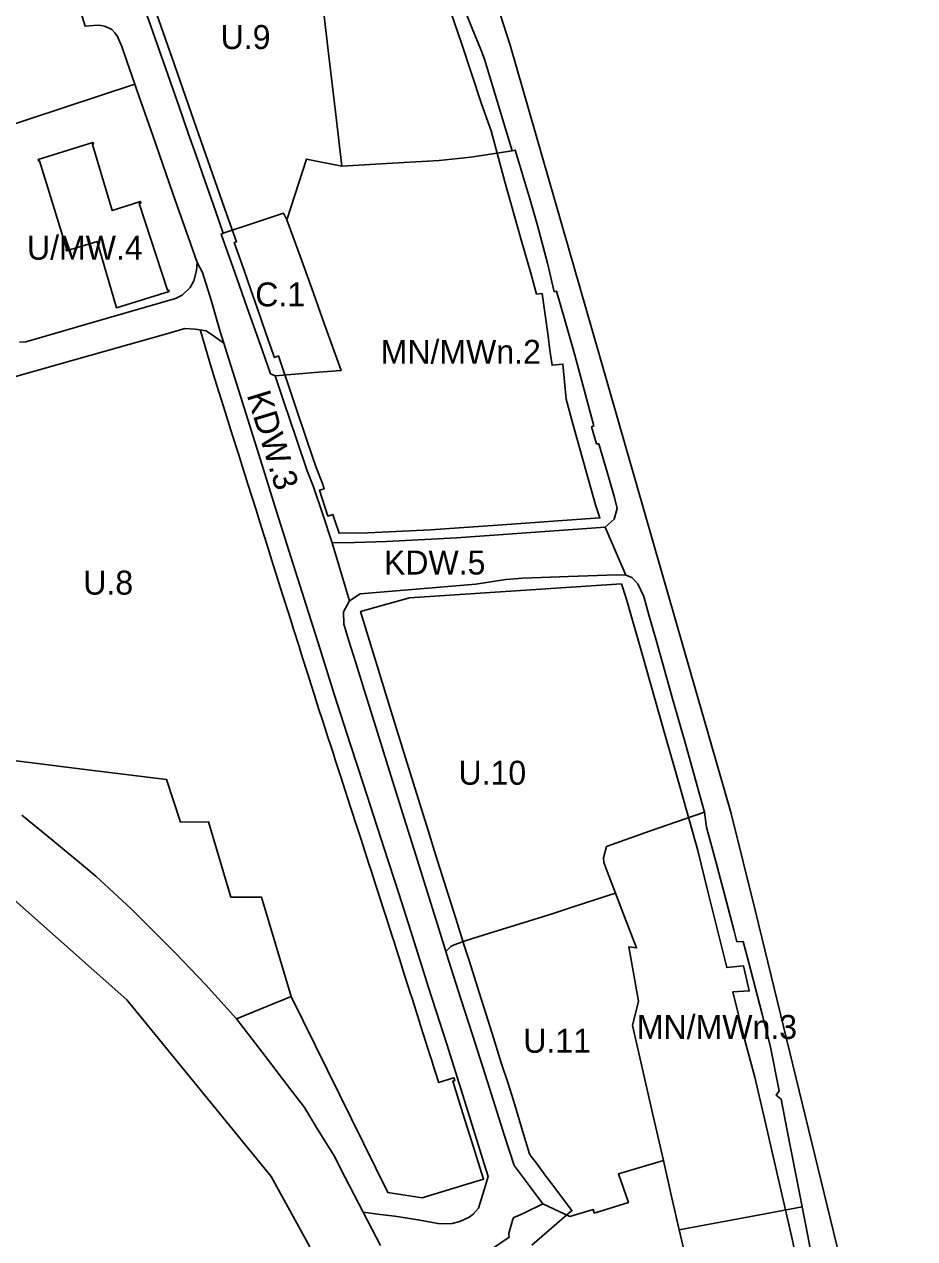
# Model space of a CAD drawing. Extents: x 7429178 to 7430831, y 5550228 to 5551611.
# Drawn here: x 7430325.9 to 7430511.7, y 5550756.2 to 5551009.6 of the extents above; entities that cross this region are included whole.
import ezdxf

# ---------------------------------------------------------------- set-up
doc = ezdxf.new("R2010")
doc.units = 0
for name, color, linetype in [('linie rozgraniczające', 7, 'Continuous'), ('nieprzekraczalne linie zabudowy', 7, 'Continuous'), ('obowiazujace linie zabudowy', 7, 'Continuous'), ('przeznaczenia terenów', 7, 'Continuous')]:
    doc.layers.add(name, color=color, linetype=linetype)

msp = doc.modelspace()

# ---------------------------------------------------------------- linework, layer by layer
at = {"layer": 'linie rozgraniczające'}
for points in [[(7430453.92, 5551228.43), (7430452.8, 5551207.06), (7430447.48, 5551184.97), (7430436.75, 5551167.9), (7430417.03, 5551148.36), (7430410.12, 5551141.52), (7430399.35, 5551124.8), (7430396.42, 5551112.21), (7430406.64, 5551069.14), (7430427.25, 5551005.18), (7430445.89, 5550940.42), (7430457.32, 5550900.71), (7430473.38, 5550844.91), (7430478.4, 5550824.47), (7430511.65, 5550687.91)], [(7430490.84, 5550748.89), (7430489.32, 5550756.73), (7430488.15, 5550762.79), (7430487.65, 5550765.35), (7430485.06, 5550778.76), (7430483.8, 5550785.25), (7430482.76, 5550786.1), (7430483.39, 5550787.04), (7430481.49, 5550796.45), (7430479.81, 5550803.02), (7430476.95, 5550813.97), (7430475.84, 5550818.16), (7430474.55, 5550818.13), (7430473.89, 5550820.64), (7430472.35, 5550826.45), (7430470.13, 5550834.85), (7430468.71, 5550840.25), (7430468.24, 5550842.03), (7430467.81, 5550845.19), (7430467.2, 5550847.36), (7430465.7, 5550852.67), (7430463.8, 5550859.39), (7430461.19, 5550868.63), (7430457.69, 5550881.02), (7430456.18, 5550886.35), (7430455.1, 5550890.19), (7430453.91, 5550892.79), (7430452.62, 5550894.11), (7430451.36, 5550894.59), (7430447.08, 5550904.63), (7430448.93, 5550906.3), (7430449.54, 5550908.55), (7430449.02, 5550910.82), (7430447.82, 5550914.91), (7430445.73, 5550922.02), (7430445.26, 5550921.99), (7430444.21, 5550925.54), (7430444.7, 5550925.75), (7430442.18, 5550935.12), (7430440.53, 5550941.29), (7430438.71, 5550947.59), (7430436.88, 5550953.89), (7430436.46, 5550953.77), (7430435.02, 5550959.71), (7430432.98, 5550967.56), (7430431.59, 5550972.44), (7430429.26, 5550980.12), (7430428.29, 5550983.33), (7430427.64, 5550983.15), (7430425.22, 5550991.24), (7430421.92, 5551002.28), (7430421.11, 5551004.3), (7430419.34, 5551008.71), (7430415.02, 5551019.47)], [(7430349.47, 5551017.13), (7430352.68, 5551007.97), (7430355.37, 5551000.28), (7430358.15, 5550992.34), (7430359.99, 5550987.07), (7430361.79, 5550981.96), (7430363.52, 5550977), (7430365.76, 5550970.62), (7430367.39, 5550965.95), (7430366.94, 5550965.8), (7430369.42, 5550958.77), (7430370.68, 5550955.2), (7430372.37, 5550950.41), (7430375.05, 5550942.82), (7430377.22, 5550936.65), (7430378.2, 5550936.24), (7430379.95, 5550931.01), (7430382.64, 5550922.96), (7430384.86, 5550916.39), (7430386.2, 5550913.03), (7430388.08, 5550907.5), (7430390.1, 5550901.33), (7430392.92, 5550892.01), (7430393.75, 5550889.28), (7430392.5, 5550887), (7430392.51, 5550884.41), (7430393.6, 5550880.91), (7430395.04, 5550876.32), (7430397.07, 5550869.79), (7430399.56, 5550861.81), (7430402.08, 5550853.74), (7430404.8, 5550845.03), (7430407.9, 5550835.07), (7430412.34, 5550820.85), (7430413.84, 5550816.07), (7430414.4, 5550814.29), (7430416.97, 5550806.2), (7430419.37, 5550798.68), (7430422.5, 5550788.87), (7430426.09, 5550777.61), (7430428.05, 5550771.46), (7430431.39, 5550766.98), (7430434.05, 5550763.41), (7430430.11, 5550761.48), (7430428.82, 5550760.9), (7430428.04, 5550760.61), (7430427.82, 5550760.24), (7430427.45, 5550758.99), (7430426.96, 5550757.3), (7430426.99, 5550756.84), (7430427.01, 5550756.46), (7430423.57, 5550754.1)], [(7430387.97, 5551015.55), (7430389.44, 5551002.92), (7430390.79, 5550991.31), (7430392.11, 5550979.97), (7430384.78, 5550981.42), (7430380.67, 5550968.74), (7430379.98, 5550970.15), (7430374.71, 5550968.39), (7430367.39, 5550965.95), (7430365.76, 5550970.62), (7430363.52, 5550977), (7430361.79, 5550981.96), (7430359.99, 5550987.07), (7430358.15, 5550992.34), (7430355.37, 5551000.28), (7430352.68, 5551007.97), (7430349.47, 5551017.13)], [(7430336.83, 5551014.89), (7430338.57, 5551009.2), (7430340.33, 5551009.32), (7430341.41, 5551009.4), (7430342.27, 5551009.24), (7430342.82, 5551009.13), (7430344.12, 5551008.49), (7430344.79, 5551007.76), (7430345.31, 5551007.03), (7430346.22, 5551004.91), (7430347.28, 5551001.86), (7430348.95, 5550997.08), (7430312.19, 5550985)], [(7430400.16, 5550754.72), (7430396.56, 5550761.69), (7430400.11, 5550761.24), (7430403.19, 5550760.85), (7430407.99, 5550760.12), (7430412.21, 5550759.3), (7430413.85, 5550759.25), (7430415.16, 5550759.34), (7430416.75, 5550759.72), (7430418.7, 5550760.68), (7430419.51, 5550761.27), (7430420.61, 5550762.53), (7430421.81, 5550766.36), (7430422.67, 5550769.11), (7430421.83, 5550771.78), (7430418.03, 5550783.91), (7430414, 5550796.74), (7430410.23, 5550808.6), (7430408.83, 5550813.01), (7430406.03, 5550821.84), (7430403.99, 5550828.17), (7430400.95, 5550837.55), (7430396.61, 5550850.97), (7430393.93, 5550859.22), (7430390.52, 5550869.76), (7430387.5, 5550879.36), (7430384.26, 5550889.67), (7430380.67, 5550901.08), (7430378.52, 5550907.93), (7430375.15, 5550918.65), (7430370.96, 5550931.95), (7430368.1, 5550941.04), (7430367.47, 5550943.06), (7430366.64, 5550945.7), (7430364.85, 5550952.03), (7430364.16, 5550954.23), (7430363.05, 5550957.79), (7430361.91, 5550959.85), (7430360.11, 5550965.03), (7430356.89, 5550974.28), (7430352.69, 5550986.34), (7430349.37, 5550995.85), (7430348.95, 5550997.08), (7430347.28, 5551001.86), (7430346.22, 5551004.91), (7430345.31, 5551007.03), (7430344.79, 5551007.76), (7430344.12, 5551008.49), (7430342.82, 5551009.13), (7430342.27, 5551009.24), (7430341.41, 5551009.4), (7430340.33, 5551009.32), (7430338.57, 5551009.2), (7430336.83, 5551014.89)], [(7430312.19, 5550985), (7430348.95, 5550997.08), (7430349.37, 5550995.85), (7430352.69, 5550986.34), (7430356.89, 5550974.28), (7430360.11, 5550965.03), (7430361.91, 5550959.85), (7430361.83, 5550958.18), (7430361.26, 5550956.01), (7430360.5, 5550954.66), (7430358.84, 5550953.01), (7430357.44, 5550952.37), (7430351.15, 5550950.54), (7430342.97, 5550948.16), (7430336.48, 5550946.26), (7430326.2, 5550943.27), (7430324.88, 5550943.21)], [(7430324.88, 5550943.21), (7430326.2, 5550943.27), (7430336.48, 5550946.26), (7430342.97, 5550948.16), (7430351.15, 5550950.54), (7430357.44, 5550952.37), (7430358.84, 5550953.01), (7430360.5, 5550954.66), (7430361.26, 5550956.01), (7430361.83, 5550958.18), (7430361.91, 5550959.85), (7430363.05, 5550957.79), (7430364.16, 5550954.23), (7430364.85, 5550952.03), (7430366.64, 5550945.7), (7430367.47, 5550943.06), (7430365.38, 5550944.54), (7430363.79, 5550945.57), (7430361.52, 5550945.94), (7430359.38, 5550946.07), (7430355.36, 5550944.93), (7430342.24, 5550941.21), (7430333.6, 5550938.76), (7430322.34, 5550935.57)], [(7430322.34, 5550935.57), (7430333.6, 5550938.76), (7430342.24, 5550941.21), (7430355.36, 5550944.93), (7430359.38, 5550946.07), (7430361.52, 5550945.94), (7430363.79, 5550945.57), (7430365.38, 5550944.54), (7430367.47, 5550943.06), (7430368.1, 5550941.04), (7430370.96, 5550931.95), (7430375.15, 5550918.65), (7430378.52, 5550907.93), (7430380.67, 5550901.08), (7430384.26, 5550889.67), (7430387.5, 5550879.36), (7430390.52, 5550869.76), (7430393.93, 5550859.22), (7430396.61, 5550850.97), (7430400.95, 5550837.55), (7430403.99, 5550828.17), (7430406.03, 5550821.84), (7430408.83, 5550813.01), (7430410.23, 5550808.6), (7430414, 5550796.74), (7430418.03, 5550783.91), (7430421.83, 5550771.78), (7430422.67, 5550769.11), (7430421.81, 5550766.36), (7430420.61, 5550762.53), (7430419.51, 5550761.27), (7430418.7, 5550760.68), (7430416.75, 5550759.72), (7430415.16, 5550759.34), (7430413.85, 5550759.25), (7430412.21, 5550759.3), (7430407.99, 5550760.12), (7430403.19, 5550760.85), (7430400.11, 5550761.24), (7430396.56, 5550761.69), (7430392.84, 5550768.9), (7430390.5, 5550773.45), (7430386.86, 5550779.4), (7430384.35, 5550783.52), (7430381.29, 5550787.51), (7430376.19, 5550794.15), (7430370.13, 5550802.02), (7430381.56, 5550806.71), (7430375.37, 5550827.45), (7430368.98, 5550827.45), (7430364.29, 5550843.15), (7430358.48, 5550843.05), (7430355.54, 5550852), (7430339.11, 5550854.01), (7430315.27, 5550857.02)], [(7430385.48, 5550754.46), (7430377.38, 5550769.13), (7430347.27, 5550805.99), (7430309.96, 5550839.07), (7430260.09, 5550864.18), (7430166.77, 5550895.04)], [(7430315.27, 5550857.02), (7430339.11, 5550854.01), (7430355.54, 5550852), (7430358.48, 5550843.05), (7430364.29, 5550843.15), (7430368.98, 5550827.45), (7430375.37, 5550827.45), (7430381.56, 5550806.71), (7430370.13, 5550802.02), (7430363.66, 5550809.19), (7430357.4, 5550815.77), (7430348.15, 5550824.96), (7430340.78, 5550831.81), (7430337.36, 5550834.69), (7430329.47, 5550841.17), (7430325.35, 5550844.54)], [(7430325.35, 5550844.54), (7430329.47, 5550841.17), (7430337.36, 5550834.69), (7430340.78, 5550831.81), (7430348.15, 5550824.96), (7430357.4, 5550815.77), (7430363.66, 5550809.19), (7430370.13, 5550802.02), (7430376.19, 5550794.15), (7430381.29, 5550787.51), (7430384.35, 5550783.52), (7430386.86, 5550779.4), (7430390.5, 5550773.45), (7430392.84, 5550768.9), (7430396.56, 5550761.69), (7430400.16, 5550754.72)], [(7430423.57, 5550754.1), (7430427.01, 5550756.46), (7430426.99, 5550756.84), (7430426.96, 5550757.3), (7430427.45, 5550758.99), (7430427.82, 5550760.24), (7430428.04, 5550760.61), (7430428.82, 5550760.9), (7430430.11, 5550761.48), (7430434.05, 5550763.41), (7430439.72, 5550760.82), (7430444.57, 5550762.23), (7430444.8, 5550761.51), (7430451.93, 5550763.7), (7430449.86, 5550769.72), (7430459.21, 5550772.49), (7430460.92, 5550764.97), (7430462.49, 5550758.04), (7430465.03, 5550747.36)]]:
    msp.add_lwpolyline(points, dxfattribs=at)
for points in [[(7430413.85, 5551022.39), (7430415.02, 5551019.47), (7430419.34, 5551008.71), (7430421.11, 5551004.3), (7430421.92, 5551002.28), (7430425.22, 5550991.24), (7430427.64, 5550983.15), (7430419.02, 5550981.87), (7430412.4, 5550981.17), (7430402.69, 5550980.57), (7430392.11, 5550979.97), (7430390.79, 5550991.31), (7430389.44, 5551002.92), (7430387.97, 5551015.55), (7430387.33, 5551021.05), (7430380.51, 5551020.7), (7430375.05, 5551038.57), (7430369.27, 5551057.75), (7430385.34, 5551059.07), (7430403.77, 5551060.54), (7430403.79, 5551060.54), (7430405.06, 5551055.65), (7430408.57, 5551042.36), (7430412.78, 5551026.44)], [(7430380.67, 5550968.74), (7430384.78, 5550981.42), (7430392.11, 5550979.97), (7430402.69, 5550980.57), (7430412.4, 5550981.17), (7430419.02, 5550981.87), (7430427.64, 5550983.15), (7430428.29, 5550983.33), (7430429.26, 5550980.12), (7430431.59, 5550972.44), (7430432.98, 5550967.56), (7430435.02, 5550959.71), (7430436.46, 5550953.77), (7430436.88, 5550953.89), (7430438.71, 5550947.59), (7430440.53, 5550941.29), (7430442.18, 5550935.12), (7430444.7, 5550925.75), (7430444.21, 5550925.54), (7430445.26, 5550921.99), (7430445.73, 5550922.02), (7430447.82, 5550914.91), (7430449.02, 5550910.82), (7430449.54, 5550908.55), (7430448.93, 5550906.3), (7430447.08, 5550904.63), (7430441.27, 5550904.22), (7430416.02, 5550902.42), (7430401.43, 5550901.65), (7430394.78, 5550901.42), (7430390.1, 5550901.33), (7430388.08, 5550907.5), (7430386.2, 5550913.03), (7430384.86, 5550916.39), (7430382.64, 5550922.96), (7430379.95, 5550931.01), (7430378.2, 5550936.24), (7430387.25, 5550937), (7430391.98, 5550937.32), (7430388.45, 5550947.16), (7430385.83, 5550954.46), (7430383.42, 5550961.15)], [(7430378.2, 5550936.24), (7430377.22, 5550936.65), (7430375.05, 5550942.82), (7430372.37, 5550950.41), (7430370.68, 5550955.2), (7430369.42, 5550958.77), (7430366.94, 5550965.8), (7430367.39, 5550965.95), (7430374.71, 5550968.39), (7430379.98, 5550970.15), (7430380.67, 5550968.74), (7430383.42, 5550961.15), (7430385.83, 5550954.46), (7430388.45, 5550947.16), (7430391.98, 5550937.32), (7430387.25, 5550937)], [(7430451.36, 5550894.59), (7430449.43, 5550894.7), (7430439.41, 5550894.34), (7430429.87, 5550893.99), (7430426.32, 5550893.72), (7430420.08, 5550892.75), (7430406.8, 5550891.63), (7430395.94, 5550890.71), (7430393.75, 5550889.28), (7430392.92, 5550892.01), (7430390.1, 5550901.33), (7430394.78, 5550901.42), (7430401.43, 5550901.65), (7430416.02, 5550902.42), (7430441.27, 5550904.22), (7430447.08, 5550904.63)], [(7430414.9, 5550817.14), (7430413.84, 5550816.07), (7430412.34, 5550820.85), (7430407.9, 5550835.07), (7430404.8, 5550845.03), (7430402.08, 5550853.74), (7430399.56, 5550861.81), (7430397.07, 5550869.79), (7430395.04, 5550876.32), (7430393.6, 5550880.91), (7430392.51, 5550884.41), (7430392.5, 5550887), (7430393.75, 5550889.28), (7430395.94, 5550890.71), (7430406.8, 5550891.63), (7430420.08, 5550892.75), (7430426.32, 5550893.72), (7430429.87, 5550893.99), (7430439.41, 5550894.34), (7430449.43, 5550894.7), (7430451.36, 5550894.59), (7430452.62, 5550894.11), (7430453.91, 5550892.79), (7430455.1, 5550890.19), (7430456.18, 5550886.35), (7430457.69, 5550881.02), (7430461.19, 5550868.63), (7430463.8, 5550859.39), (7430465.7, 5550852.67), (7430467.2, 5550847.36), (7430467.81, 5550845.19), (7430456.31, 5550841.22), (7430447.34, 5550838.02), (7430446.69, 5550835.65), (7430446.76, 5550834.63), (7430447.81, 5550831.91), (7430449.21, 5550828.29), (7430447.72, 5550827.8), (7430440.17, 5550825.31), (7430436.25, 5550824.02), (7430429.07, 5550821.79), (7430422.94, 5550819.89), (7430418.06, 5550818.37), (7430415.58, 5550817.48)], [(7430473.89, 5550820.64), (7430474.55, 5550818.13), (7430475.84, 5550818.16), (7430476.95, 5550813.97), (7430479.81, 5550803.02), (7430481.49, 5550796.45), (7430483.39, 5550787.04), (7430482.76, 5550786.1), (7430483.8, 5550785.25), (7430485.06, 5550778.76), (7430487.65, 5550765.35), (7430488.15, 5550762.79), (7430480.48, 5550761.37), (7430467.74, 5550759.02), (7430462.49, 5550758.04), (7430460.92, 5550764.97), (7430459.21, 5550772.49), (7430457.18, 5550781.42), (7430454.31, 5550793.96), (7430452.78, 5550800.65), (7430453.99, 5550805.71), (7430452.03, 5550817.08), (7430453.63, 5550816.83), (7430451.12, 5550823.35), (7430449.21, 5550828.29), (7430447.81, 5550831.91), (7430446.76, 5550834.63), (7430446.69, 5550835.65), (7430447.34, 5550838.02), (7430456.31, 5550841.22), (7430467.81, 5550845.19), (7430468.24, 5550842.03), (7430468.71, 5550840.25), (7430470.13, 5550834.85), (7430472.35, 5550826.45)], [(7430451.12, 5550823.35), (7430453.63, 5550816.83), (7430452.03, 5550817.08), (7430453.99, 5550805.71), (7430452.78, 5550800.65), (7430454.31, 5550793.96), (7430457.18, 5550781.42), (7430459.21, 5550772.49), (7430449.86, 5550769.72), (7430451.93, 5550763.7), (7430444.8, 5550761.51), (7430444.57, 5550762.23), (7430439.72, 5550760.82), (7430434.05, 5550763.41), (7430431.39, 5550766.98), (7430428.05, 5550771.46), (7430426.09, 5550777.61), (7430422.5, 5550788.87), (7430419.37, 5550798.68), (7430416.97, 5550806.2), (7430414.4, 5550814.29), (7430413.84, 5550816.07), (7430414.9, 5550817.14), (7430415.58, 5550817.48), (7430418.06, 5550818.37), (7430422.94, 5550819.89), (7430429.07, 5550821.79), (7430436.25, 5550824.02), (7430440.17, 5550825.31), (7430447.72, 5550827.8), (7430449.21, 5550828.29)], [(7430477.72, 5550741.09), (7430466.68, 5550740.4), (7430465.03, 5550747.36), (7430462.49, 5550758.04), (7430467.74, 5550759.02), (7430480.48, 5550761.37), (7430488.15, 5550762.79), (7430489.32, 5550756.73), (7430490.84, 5550748.89), (7430492.17, 5550742)]]:
    msp.add_lwpolyline(points, close=True, dxfattribs=at)
at = {"layer": 'nieprzekraczalne linie zabudowy'}
for points in [[(7430350.8, 5551019.4), (7430356.64, 5551002.71), (7430361.27, 5550989.49), (7430368.16, 5550969.81), (7430370.13, 5550964.19), (7430369.69, 5550964.04), (7430371.67, 5550958.38), (7430373.16, 5550954.12), (7430374.46, 5550950.4), (7430376.3, 5550945.13), (7430377.87, 5550940.62), (7430378.07, 5550940.06), (7430378.94, 5550940.36), (7430385.02, 5550922.16), (7430386.74, 5550917.08), (7430388.08, 5550913.72), (7430388.44, 5550912.66), (7430387.46, 5550912.34), (7430389.19, 5550906.94), (7430390.25, 5550907.28), (7430390.66, 5550906.04), (7430391.54, 5550903.36), (7430397.57, 5550903.48), (7430410.63, 5550904.05), (7430424.58, 5550905.04), (7430445.96, 5550906.56), (7430445.06, 5550909.32), (7430440.34, 5550926.22), (7430438.94, 5550931.34), (7430438.26, 5550938.67), (7430435.98, 5550938.43), (7430435.51, 5550941.58), (7430435.14, 5550944.46), (7430433.91, 5550953.4), (7430432.76, 5550953.25), (7430431.58, 5550957.64), (7430429.52, 5550964.56), (7430426.12, 5550976.71), (7430423.28, 5550987.31), (7430421.28, 5550992.97), (7430417.06, 5551005.59), (7430413.54, 5551015.99)], [(7430381.56, 5550806.71), (7430401.71, 5550765.8), (7430408.89, 5550764.7), (7430417.97, 5550767.47), (7430421.69, 5550768.61), (7430419.17, 5550776.6), (7430417.37, 5550782.3), (7430415.26, 5550789.01), (7430415.69, 5550789.15), (7430415.51, 5550789.74), (7430412.32, 5550788.74), (7430412.21, 5550789.09), (7430411.73, 5550790.63), (7430411.34, 5550791.88), (7430410.81, 5550793.54), (7430410.5, 5550794.53), (7430410.15, 5550795.64), (7430409.94, 5550796.29), (7430409.25, 5550798.47), (7430408.49, 5550800.86), (7430408.25, 5550801.62), (7430407.62, 5550803.62), (7430406.77, 5550806.29), (7430406.32, 5550807.7), (7430405.98, 5550808.77), (7430405.23, 5550811.14), (7430404.66, 5550812.94), (7430404.14, 5550814.58), (7430403.39, 5550816.93), (7430402.94, 5550818.35), (7430402.72, 5550819.05), (7430401.39, 5550823.24), (7430400.84, 5550824.92), (7430399.78, 5550828.19), (7430399.31, 5550829.66), (7430398.3, 5550832.76), (7430397.77, 5550834.41), (7430396.57, 5550838.11), (7430396.07, 5550839.66), (7430394.92, 5550843.19), (7430394.36, 5550844.93), (7430393.87, 5550846.43), (7430392.9, 5550849.45), (7430392.33, 5550851.2), (7430391.88, 5550852.57), (7430390.74, 5550856.09), (7430390.35, 5550857.32), (7430389.94, 5550858.56), (7430389.14, 5550861.05), (7430388.7, 5550862.39), (7430387.99, 5550864.58), (7430387.35, 5550866.57), (7430386.7, 5550868.58), (7430386.39, 5550869.55), (7430385.63, 5550871.97), (7430385.02, 5550873.93), (7430384.69, 5550874.98), (7430384.13, 5550876.76), (7430383.65, 5550878.27), (7430383.2, 5550879.71), (7430382.05, 5550883.37), (7430381.47, 5550885.2), (7430380.79, 5550887.37), (7430380.17, 5550889.34), (7430379.77, 5550890.61), (7430378.37, 5550895.06), (7430377.83, 5550896.79), (7430376.47, 5550901.09), (7430375.03, 5550905.69), (7430374.22, 5550908.25), (7430372.54, 5550913.62), (7430371.34, 5550917.42), (7430370.49, 5550920.12), (7430369.34, 5550923.78), (7430367.45, 5550929.8), (7430366, 5550934.4), (7430364.64, 5550938.72), (7430362.56, 5550945.88)], [(7430488.44, 5550745.28), (7430486.02, 5550756.44), (7430483.81, 5550766.05), (7430480.4, 5550780.87), (7430478.28, 5550789.87), (7430476.03, 5550798.36), (7430473.71, 5550807.64), (7430477.13, 5550807.86), (7430475.94, 5550813.08), (7430472.44, 5550812.75), (7430471.89, 5550814.96), (7430468.51, 5550828.58), (7430466.39, 5550837.15), (7430462.81, 5550850.05), (7430459.36, 5550861.95), (7430454.6, 5550878.89), (7430451.72, 5550888.84), (7430451.35, 5550890.05), (7430450.46, 5550892.78), (7430406.25, 5550889.88), (7430396.03, 5550887.01), (7430401.87, 5550867.98), (7430403.28, 5550863.45), (7430405.4, 5550856.53), (7430407.38, 5550850.21), (7430409.84, 5550842.25), (7430411.77, 5550836.1), (7430413.89, 5550829.31), (7430415.88, 5550822.96), (7430417.62, 5550817.33), (7430418.69, 5550814.23), (7430420.87, 5550807.35), (7430423.49, 5550798.96), (7430425.4, 5550792.85), (7430426.82, 5550788.58), (7430428.23, 5550784.11), (7430429.84, 5550778.65), (7430431, 5550774.8), (7430431.25, 5550773.9), (7430431.66, 5550773.31), (7430432.71, 5550771.9), (7430434.7, 5550769.24), (7430435.85, 5550767.69), (7430440.13, 5550762.04), (7430431.8, 5550754.82)]]:
    msp.add_lwpolyline(points, dxfattribs=at)
at = {"layer": 'obowiazujace linie zabudowy'}
msp.add_lwpolyline([(7430328.76, 5550981.33), (7430328.84, 5550981.03), (7430329.02, 5550981.09), (7430334.77, 5550962.59), (7430334.55, 5550962.54), (7430334.69, 5550962.28), (7430341.06, 5550964.26), (7430345.13, 5550950.41), (7430356.07, 5550953.81), (7430355.95, 5550954.15), (7430355.72, 5550954.08), (7430349.86, 5550972.15), (7430350.21, 5550972.24), (7430350.11, 5550972.59), (7430344.23, 5550970.7), (7430340.09, 5550984.5), (7430340.28, 5550984.55), (7430340.19, 5550984.87), (7430328.76, 5550981.33)], dxfattribs=at)

# ---------------------------------------------------------------- texts
at = {"layer": 'przeznaczenia terenów'}
for s, p in [('U.9', (7430366.84, 5551004.4)), ('U/MW.4', (7430326.43, 5550960.44)), ('C.1', (7430374.06, 5550950.69)), ('MN/MWn.2', (7430400.22, 5550938.72)), ('KDW.5', (7430400.91, 5550894.75)), ('U.8', (7430338.18, 5550890.56)), ('U.10', (7430416.46, 5550850.89)), ('MN/MWn.3', (7430453.67, 5550797.84)), ('U.11', (7430429.99, 5550794.96))]:
    msp.add_text(s, height=5, dxfattribs=at).set_placement(p)
msp.add_text('KDW.3', height=5, rotation=286.9646, dxfattribs=at).set_placement((7430372.25, 5550932.23))

doc.saveas('drawing.dxf')
